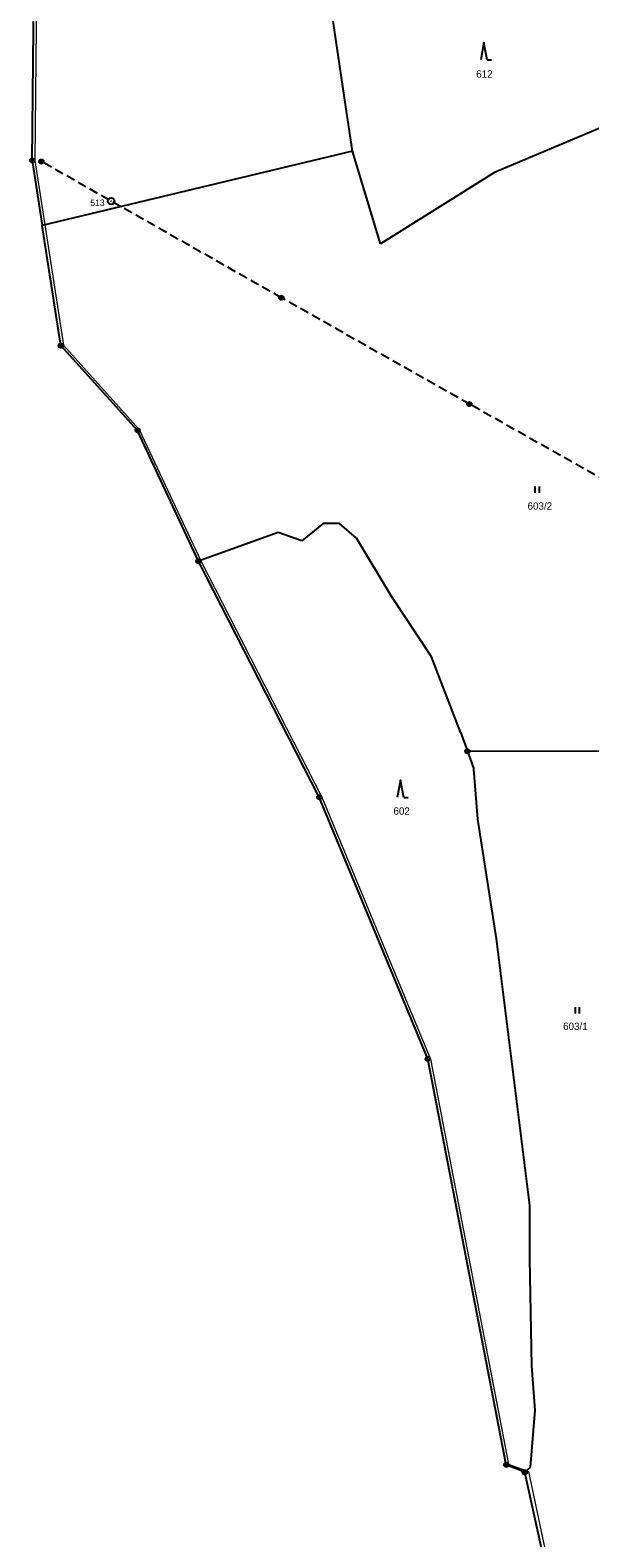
# Model space of a CAD drawing. Extents: x -653193 to -651624, y -1092017 to -1090260.
# Drawn here: x -653193.1 to -653063.5, y -1091598.3 to -1091249.7 of the extents above; entities that cross this region are included whole.
import ezdxf
from ezdxf.enums import TextEntityAlignment as Align

# ---------------------------------------------------------------- set-up
doc = ezdxf.new("R2010")
doc.units = 0
doc.header["$LTSCALE"] = 0.68
doc.linetypes.add('MEDIUM_DASHED', pattern=[4.5, 3, -1.5])
for name, color, linetype, lineweight in [('1', 7, 'Continuous', 25), ('3', 7, 'Continuous', 25), ('4', 7, 'Continuous', 13), ('6', 7, 'Continuous', 25), ('8', 7, 'Continuous', 25)]:
    doc.layers.add(name, color=color, linetype=linetype, lineweight=lineweight)
doc.layers.add('2', color=7, linetype='Continuous')

msp = doc.modelspace()

# ---------------------------------------------------------------- linework, layer by layer
at = {"layer": '1'}
for p, q in [((-653192.6, -1091279.83), (-653191.83, -1091202.49)), ((-653120.1, -1091266.89), (-653123.34, -1091244.98)), ((-653118.5, -1091277.67), (-653120.1, -1091266.89)), ((-653057.71, -1091270.93), (-653085.61, -1091282.61)), ((-653118.5, -1091277.67), (-653190.28, -1091294.85)), ((-653111.95, -1091299.11), (-653118.5, -1091277.67)), ((-653192.6, -1091279.83), (-653190.28, -1091294.85)), ((-653085.61, -1091282.61), (-653111.95, -1091299.11)), ((-653154.15, -1091372.51), (-653168.22, -1091342.24)), ((-653135.7, -1091365.82), (-653154.15, -1091372.51)), ((-653130.2, -1091367.81), (-653135.7, -1091365.82)), ((-653125.24, -1091363.76), (-653130.2, -1091367.81)), ((-653121.49, -1091363.78), (-653125.24, -1091363.76)), ((-653117.57, -1091367.15), (-653121.49, -1091363.78)), ((-653109.48, -1091380.5), (-653117.57, -1091367.15)), ((-653126.16, -1091427.06), (-653154.15, -1091372.51)), ((-653100.17, -1091394.57), (-653109.48, -1091380.5)), ((-653093.45, -1091412.06), (-653100.17, -1091394.57)), ((-653093.45, -1091412.06), (-653091.87, -1091416.43)), ((-653091.87, -1091416.43), (-653047.2, -1091416.3)), ((-653091.87, -1091416.43), (-653090.36, -1091420.6)), ((-653089.42, -1091432.1), (-653090.36, -1091420.6)), ((-653101.03, -1091487.56), (-653126.16, -1091427.06)), ((-653085.14, -1091459.8), (-653089.42, -1091432.1)), ((-653077.38, -1091521.43), (-653085.14, -1091459.8)), ((-653082.86, -1091581.42), (-653101.03, -1091487.56)), ((-653077.43, -1091533.82), (-653077.38, -1091521.43)), ((-653076.96, -1091558.53), (-653077.43, -1091533.82)), ((-653076.16, -1091568.81), (-653076.96, -1091558.53)), ((-653077.29, -1091581.98), (-653076.16, -1091568.81)), ((-653078.57, -1091583.12), (-653082.86, -1091581.42))]:
    msp.add_line(p, q, dxfattribs=at)
for points in [[(-653168.22, -1091342.24), (-653185.99, -1091322.65), (-653190.28, -1091294.85)], [(-653070.97, -1091617.5), (-653078.57, -1091583.12), (-653077.29, -1091581.98)]]:
    msp.add_lwpolyline(points, dxfattribs=at)
at = {"layer": '3'}
for p, q in [((-653087.27, -1091256.54), (-653086.274, -1091256.54)), ((-653076.141, -1091356.7), (-653076.141, -1091355.2)), ((-653075.14, -1091356.7), (-653075.14, -1091355.2)), ((-653106.6, -1091427.13), (-653105.604, -1091427.13)), ((-653066.871, -1091477.1), (-653066.871, -1091475.6)), ((-653065.87, -1091477.1), (-653065.87, -1091475.6))]:
    msp.add_line(p, q, dxfattribs=at)
for points in [[(-653087.27, -1091256.54), (-653088.02, -1091252.54), (-653088.77, -1091256.54)], [(-653106.6, -1091427.13), (-653107.35, -1091423.13), (-653108.1, -1091427.13)]]:
    msp.add_lwpolyline(points, dxfattribs=at)
at = {"layer": '4'}
msp.add_lwpolyline([(-653150.38, -1090948.47), (-653165.77, -1090979.18), (-653165.35, -1091011.56), (-653161.74, -1091026.92), (-653176.52, -1091128.14), (-653178.05, -1091139.13), (-653181.58, -1091166.64), (-653191.27, -1091202.57), (-653191.99, -1091279.86), (-653185.4, -1091322.52), (-653167.88, -1091342.01), (-653153.56, -1091372.39), (-653125.53, -1091427.08), (-653100.42, -1091487.61), (-653082.33, -1091581.28), (-653077.75, -1091583), (-653070.49, -1091617.25)], dxfattribs=at)
at = {"layer": '6', "linetype": 'MEDIUM_DASHED'}
for p, q in [((-653134.92, -1091311.59), (-653190.49, -1091280.08)), ((-653091.4, -1091336.17), (-653134.92, -1091311.59)), ((-653043.67, -1091363.03), (-653091.4, -1091336.17))]:
    msp.add_line(p, q, dxfattribs=at)
at = {"layer": '6'}
for centre, radius in [((-653190.4934, -1091280.0799), 0.5), ((-653190.4934, -1091280.0799), 0.4), ((-653190.4934, -1091280.0799), 0.3), ((-653190.4934, -1091280.0799), 0.2), ((-653190.4934, -1091280.0799), 0.1), ((-653134.9234, -1091311.5899), 0.5), ((-653134.9234, -1091311.5899), 0.4), ((-653134.9234, -1091311.5899), 0.3), ((-653134.9234, -1091311.5899), 0.2), ((-653134.9234, -1091311.5899), 0.1), ((-653091.4034, -1091336.1699), 0.5), ((-653091.4034, -1091336.1699), 0.4), ((-653091.4034, -1091336.1699), 0.3), ((-653091.4034, -1091336.1699), 0.2), ((-653091.4034, -1091336.1699), 0.1)]:
    msp.add_circle(centre, radius, dxfattribs=at)
at = {"layer": '8'}
for centre, radius in [((-653192.6, -1091279.8299), 0.5), ((-653192.6, -1091279.8299), 0.0303), ((-653174.34, -1091289.2498), 0.75), ((-653174.34, -1091289.2498), 0.03), ((-653185.99, -1091322.6499), 0.5), ((-653185.99, -1091322.6499), 0.0303), ((-653168.22, -1091342.2399), 0.5), ((-653168.22, -1091342.2399), 0.0303), ((-653154.15, -1091372.5099), 0.5), ((-653154.15, -1091372.5099), 0.0303), ((-653091.87, -1091416.4299), 0.5), ((-653091.87, -1091416.4299), 0.0303), ((-653126.16, -1091427.0599), 0.5), ((-653126.16, -1091427.0599), 0.0303), ((-653101.03, -1091487.5599), 0.5), ((-653101.03, -1091487.5599), 0.0303), ((-653082.86, -1091581.4199), 0.5), ((-653082.86, -1091581.4199), 0.0303), ((-653078.57, -1091583.1199), 0.5), ((-653078.57, -1091583.1199), 0.0303)]:
    msp.add_circle(centre, radius, dxfattribs=at)

# ---------------------------------------------------------------- texts
at = {"layer": '2'}
for s, p in [('612', (-653087.929, -1091260.695)), ('603/2', (-653075.09, -1091360.585)), ('602', (-653107.079, -1091431.105)), ('603/1', (-653066.86, -1091480.885))]:
    msp.add_text(s, height=1.7, dxfattribs=at).set_placement(p, align=Align.CENTER)
at = {"layer": '8'}
msp.add_text('513', height=1.5, dxfattribs=at).set_placement((-653175.839, -1091290.367), align=Align.RIGHT)

doc.saveas('drawing.dxf')
